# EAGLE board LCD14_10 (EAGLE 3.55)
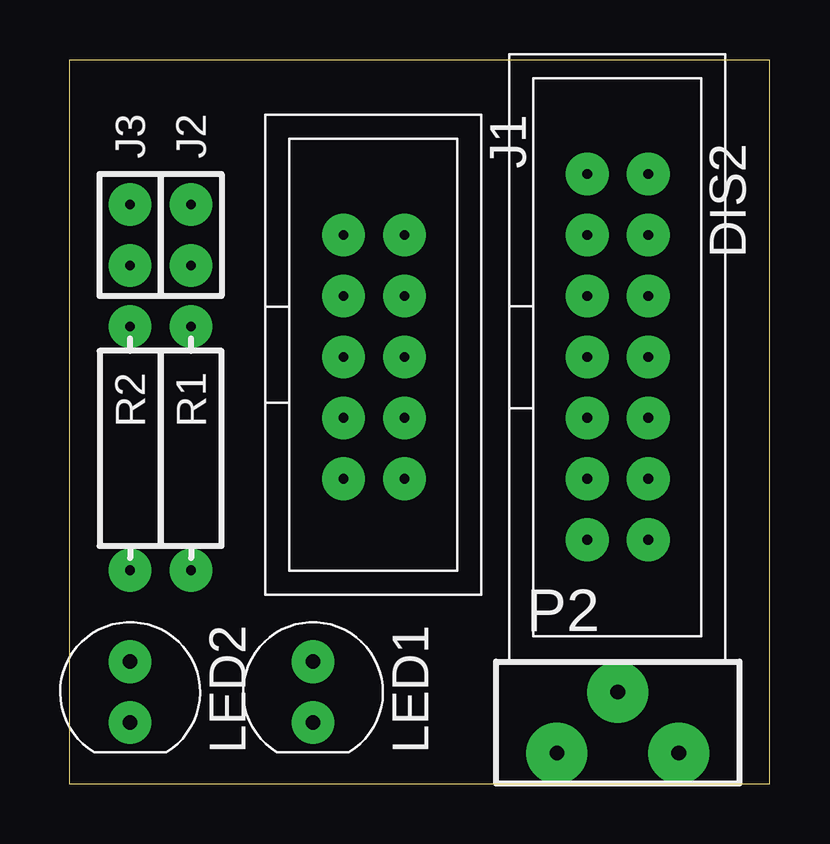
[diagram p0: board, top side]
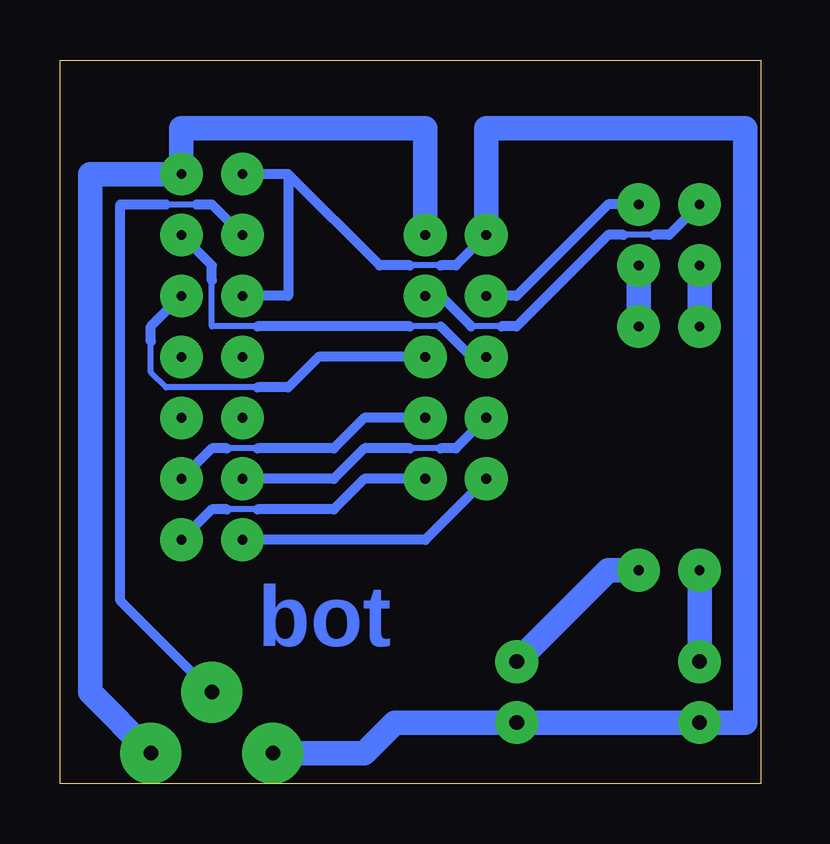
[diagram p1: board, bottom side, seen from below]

Size 29.19 x 30.15 mm. Coordinates in mm from the lower left corner, seen from the top.
Outline: 0,0 29.19,0 29.19,30.15 0,30.15 0,0
Copper layers used: Bottom

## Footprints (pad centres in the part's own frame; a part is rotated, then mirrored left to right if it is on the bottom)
7 = drill 0.406 pad 1.778 round:  0,0;  2.54,0;  5.08,0;  7.62,0;  10.16,0;  10.16,2.54;  7.62,2.54;  5.08,2.54;  2.54,2.54;  0,2.54;  12.7,0;  12.7,2.54;  15.24,0;  15.24,2.54
5 = drill 0.406 pad 1.778 round:  0,0;  2.54,0;  5.08,0;  7.62,0;  10.16,0;  10.16,2.54;  7.62,2.54;  5.08,2.54;  2.54,2.54;  0,2.54
MPER = drill 0.406 pad 1.778 round:  -1.27,0;  1.27,0
D_5MM = drill 0.61 pad 1.778 round:  -1.27,0;  1.27,0
IM_STE = drill 0.61 pad 2.54 round:  -2.54,-1.27;  2.54,-1.27;  0,1.27
S04 = drill 0.406 pad 1.778 round:  -5.08,0;  5.08,0

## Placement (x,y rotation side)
DIS2  LCD Out  [7]  21.59,25.4 270 top
J1  8BITPORT  [5]  11.43,22.86 270 top
J2  JUMPER  [MPER]  5.08,22.86 90 top
J3  JUMPER  [MPER]  2.54,22.86 90 top
LED1  red  [D_5MM]  10.16,3.81 270 top
LED2  green  [D_5MM]  2.54,3.81 270 top
P2  47k  [IM_STE]  22.86,2.54 0 top
R1  1k  [S04]  5.08,13.97 270 top
R2  1k  [S04]  2.54,13.97 270 top

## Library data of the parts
DIS2 J1-J3 LED1 LED2 P2 R1 R2 = holg_plt

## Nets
+5V: DIS2. J1. P2.
GND: DIS2. J1. LED1. LED2. P2.
N$1: DIS2. J1.
N$2: DIS2. J1.
N$5: DIS2. P2.
N$6: J1. J2.
N$7: DIS2. J1.
N$8: DIS2. J1.
N$9: DIS2. J1.
N$10: DIS2. J1.
N$11: J1. J3.
N$12: J2. R1.
N$13: J3. R2.
N$14: LED1. R1.
N$15: LED2. R2.

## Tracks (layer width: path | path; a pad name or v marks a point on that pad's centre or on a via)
+5V
  Bottom 1.016: 25.4,1.27 27.94,3.81 27.94,25.4 24.13,25.4 24.13,27.3 13.97,27.3 J1.
GND
  Bottom 0.254: 13.34,21.59 14.61,21.59
  Bottom 0.406: 19.68,25.4 15.88,21.59 14.61,21.59 | 11.43,22.86 12.7,21.59 13.34,21.59 | 19.68,25.4 21.59,25.4 | 19.68,25.4 19.68,20.32 21.59,20.32
  Bottom 1.016: 20.32,1.27 16.51,1.27 15.24,2.54 LED1. LED2. 0.64,2.54 0.64,27.3 11.43,27.3 11.43,22.86
N$1
  Bottom 0.254: 25.4,18.41 25.4,17.14 24.77,16.51 20.95,16.51
  Bottom 0.406: 13.97,17.78 18.41,17.78 19.68,16.51 20.95,16.51 | 24.13,20.32 25.4,19.05 25.4,18.41
N$2
  Bottom 0.254: 13.34,19.05 14.61,19.05 | 20.95,19.05 22.86,19.05 22.86,20.95
  Bottom 0.406: 11.43,17.78 12.06,17.78 13.34,19.05 | 24.13,22.86 22.86,21.59 22.86,20.95 | 14.61,19.05 20.95,19.05
N$5
  Bottom 0.254: 24.77,24.13 23.5,24.13
  Bottom 0.406: 21.59,22.86 22.86,24.13 23.5,24.13 | 24.77,24.13 26.67,24.13 26.67,7.62 P2.
N$6
  Bottom 0.406: 11.43,20.32 10.16,20.32 6.35,24.13 J2.
N$7
  Bottom 0.254: 13.34,13.97 14.61,13.97
  Bottom 0.406: 11.43,15.24 12.7,13.97 13.34,13.97 | 21.59,12.7 17.78,12.7 16.51,13.97 14.61,13.97
N$8
  Bottom 0.254: 20.95,13.97 22.23,13.97
  Bottom 0.406: 13.97,15.24 16.51,15.24 17.78,13.97 20.95,13.97 | 24.13,12.7 22.86,13.97 22.23,13.97
N$9
  Bottom 0.406: 21.59,10.16 13.97,10.16 11.43,12.7
N$10
  Bottom 0.254: 20.95,11.43 22.23,11.43
  Bottom 0.406: 13.97,12.7 16.51,12.7 17.78,11.43 20.95,11.43 | DIS2. 22.86,11.43 22.23,11.43
N$11
  Bottom 0.254: 4.45,22.86 5.71,22.86 | 10.79,19.05 12.06,19.05
  Bottom 0.406: J3. 3.81,22.86 4.45,22.86 | 10.79,19.05 10.16,19.05 6.35,22.86 5.71,22.86 | 13.97,20.32 13.34,20.32 12.06,19.05
N$12
  Bottom 1.016: 5.08,19.05 5.08,21.59
N$13
  Bottom 1.016: 2.54,19.05 2.54,21.59
N$14
  Bottom 1.016: R1. 6.35,8.89 10.16,5.08
N$15
  Bottom 1.016: 2.54,5.08 R2.

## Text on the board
Bottom: bot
